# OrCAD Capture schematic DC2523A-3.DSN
size Custom; title: DUAL CHANNEL 8.5A, 18V SYNCHRONOUS STEP-DOWN; rev: 3; note: DC2523A
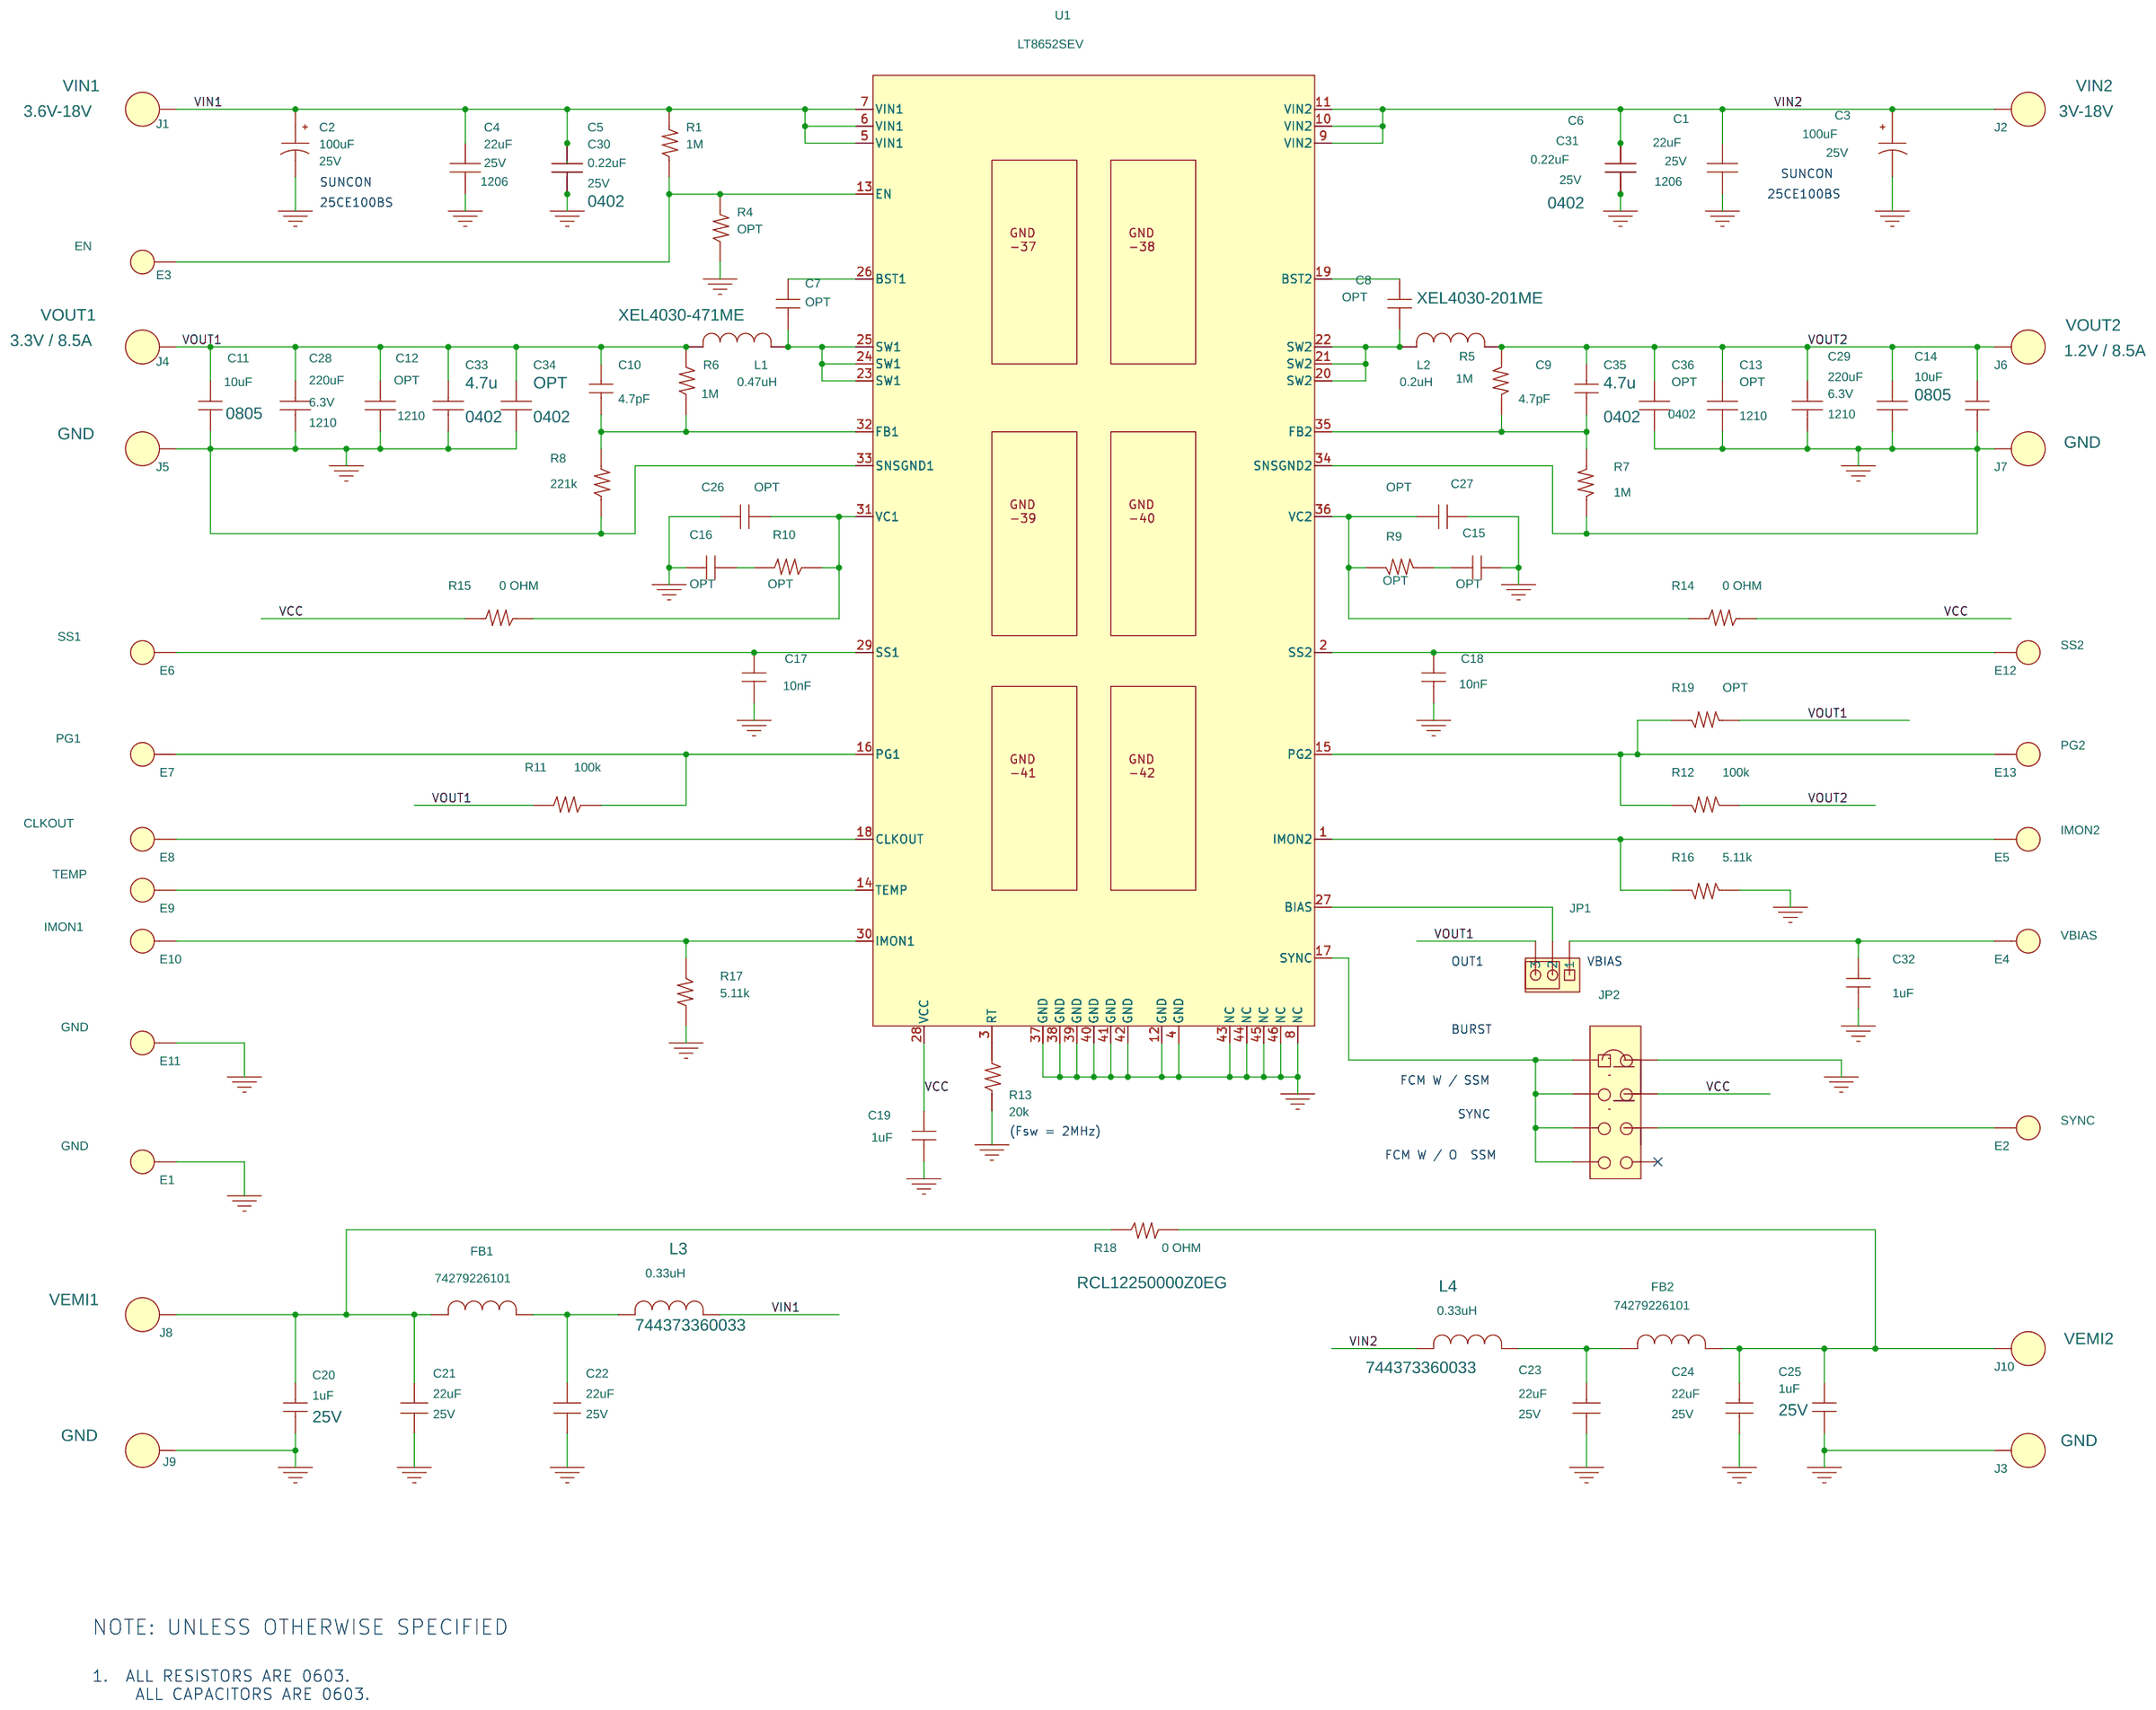
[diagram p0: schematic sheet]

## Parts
C1  22uF  [1206]
C2  100uF  [CAP-CE-BS-6.3X7.7]
C3  100uF  [CAP-CE-BS-6.3X7.7]
C4  22uF  [1206]
C5  0.22uF  [0402]
C6  0.22uF  [0402]
C7  OPT  [0603]
C8  OPT  [0603]
C9  4.7pF  [0603]
C10  4.7pF  [0603]
C11  10uF  [0805]
C12  OPT  [1210]
C13  OPT  [1210]
C14  10uF  [0805]
C15  OPT  [0603]
C16  OPT  [0603]
C17  10nF  [0603]
C18  10nF  [0603]
C19  1uF  [0603]
C20  1uF  [0603]
C21  22uF  [1210]
C22  22uF  [1210]
C23  22uF  [1210]
C24  22uF  [1210]
C25  1uF  [0603]
C26  OPT  [0603]
C27  OPT  [0603]
C28  220uF  [1210]
C29  220uF  [1210]
C30  0.22uF  [0402]
C31  0.22uF  [0402]
C32  1uF  [0603]
C33  4.7u  [0402]
C34  OPT  [0402]
C35  4.7u  [0402]
C36  OPT  [0402]
E1  PAD150-094  [PAD150-094]
E2  PAD150-094  [PAD150-094]
E3  PAD150-094  [PAD150-094]
E4  PAD150-094  [PAD150-094]
E5  PAD150-094  [PAD150-094]
E6  PAD150-094  [PAD150-094]
E7  PAD150-094  [PAD150-094]
E8  PAD150-094  [PAD150-094]
E9  PAD150-094  [PAD150-094]
E10  PAD150-094  [PAD150-094]
E11  PAD150-094  [PAD150-094]
E12  PAD150-094  [PAD150-094]
E13  PAD150-094  [PAD150-094]
FB1  74279226101  [BEAD74279226101]
FB2  74279226101  [BEAD74279226101]
J1  BANANA-JACK  [KEY-575-4]
J2  BANANA-JACK  [KEY-575-4]
J3  BANANA-JACK  [KEY-575-4]
J4  BANANA-JACK  [KEY-575-4]
J5  BANANA-JACK  [KEY-575-4]
J6  BANANA-JACK  [KEY-575-4]
J7  BANANA-JACK  [KEY-575-4]
J8  BANANA-JACK  [KEY-575-4]
J9  BANANA-JACK  [KEY-575-4]
J10  BANANA-JACK  [KEY-575-4]
JP1  JP3X1/079  [JP3X1/079]
JP2  JP2X3/079  [JP2X4/079]
L1  0.47uH  [IND-XEL4030]
L2  0.2uH  [IND-XEL4030]
L3  0.33uH  [IND-744373360033]
L4  0.33uH  [IND-744373360033]
R1  1M  [0603]
R4  OPT  [0603]
R5  1M  [0603]
R6  1M  [0603]
R7  1M  [0603]
R8  221k  [0603]
R9  OPT  [0603]
R10  OPT  [0603]
R11  100k  [0603]
R12  100k  [0603]
R13  20k  [0603]
R14  0 OHM  [0603]
R15  0 OHM  [0603]
R16  5.11k  [0603]
R17  5.11k  [0603]
R18  0 OHM  [RES-RCL1225E3]
R19  OPT  [0603]
U1  LT8652SEV  [LGA-36/46-7X4]

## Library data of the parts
C1 = UMK325BJ105MH: CAP., 22uF, X5R, 25V, ±10%, 1206; 1st Part Field: 25V; 2nd Part Field: ±10%,; 3rd Part Field: X5R,; 4th Part Field: MURATA,; 5th Part Field: GRM31CR61H106KA12L; Part Number: MURATA, GRM31CR61H106KA12L
C2 = 50CE10BSS_1: CAP., 100uF, ALUM, 25V; 1st Part Field: 25V; 2nd Part Field: ±10%,; 3rd Part Field: Alum,; 4th Part Field: SUNCON,; 5th Part Field: 25CE100BS; 6th Part Field: (Opt); Part Number: SUN ELECT., 25CE22BS
C3 = 50CE10BSS: CAP., 100uF, ALUM, 25V; 1st Part Field: 25V; 2nd Part Field: ±10%,; 3rd Part Field: Alum,; 4th Part Field: SUNCON,; 5th Part Field: 25CE100BS; 6th Part Field: (Opt); Part Number: SUN ELECT., 25CE22BS
C4 = UMK325BJ105MH_0: CAP., 22uF, X5R,25V, ±10%, 1206; 1st Part Field: 25V; 2nd Part Field: ±10%,; 3rd Part Field: X5R,; 4th Part Field: MURATA,; 5th Part Field: GRM31CR61H106KA12L; Part Number: MURATA, GRM31CR61H106KA12L
C5 C6 = UMK325BJ105MH: CAP.,  0.22uF,X5R,25V,±10%,0402; 1st Part Field: 25V
C7 C8 = CAP-NP: CAP.,  OPT, 0603; 1st Part Field: 25V; 2nd Part Field: ±10%,; 3rd Part Field: X7R,; 4th Part Field: MURATA,; 5th Part Field: GRM188R71E104KA01D; 7th Part Field: Cap.,; Part Number: MURATA, GRM188R71E104KA01D
C9 C10 = CAP-NP: CAP., 4.7pF, C0G, 50V, ±0.25pF, 0603; 1st Part Field: 50V; 2nd Part Field: ±0.25pF,; 3rd Part Field: C0G; 4th Part Field: MURATA,; 5th Part Field: GRM1885C1H4R7CA01D; 7th Part Field: Cap.,; Part Number: MURATA, GRM1885C1H4R7CA01D
C11 C14 = CAP-NP: CAP., 10uF, X7R, 10V, 10%, 0805; 1st Part Field: 10V; 2nd Part Field: ±10%,; 3rd Part Field: X7R,; 4th Part Field: MURATA,; 5th Part Field: GRM21BR71A106KE51K; 7th Part Field: Cap.,; Part Number: MURATA, GRM21BR71A106KE51K
C12 C13 = UMK325BJ105MH: CAP.,OPT,1210
C15 = CAP-NP: CAP., 1000pF,25V, 0603; 1st Part Field: TBD; 7th Part Field: Cap.,; Discription: CAP., 1000pF, 25V 0603
C16 = CAP-NP: 1st Part Field: TBD; 7th Part Field: Cap.,; Discription: CAP., 1000pF, 25V 0603
C17 = CAP-NP: CAP., 10nF, X7R, 25V, 10%, 0603; 1st Part Field: 25V; 2nd Part Field: ±10%,; 3rd Part Field: X7R,; 4th Part Field: MURATA,; 5th Part Field: GRM188R71E103KA01D; 7th Part Field: Cap.,; Part Number: MURATA, GRM188R71E103KA01D
C18 = CAP-NP: CAP., 10nF, X7R, 25V, 10%, 0603; 1st Part Field: 25V; 2nd Part Field: ±10%,; 3rd Part Field: X7R,; 4th Part Field: MURATA,; 5th Part Field: GRM188R71E103KA01D; 7th Part Field: CAP.,; Part Number: MURATA, GRM188R71E103KA01D
C19 C20 C25 C32 = CAP-NP: CAP., 1uF, X7R, 25V, 10%, 0603; 1ST PART FIELD: 25V; 2nd Part Field: ±10%,; 3rd Part Field: X7R,; 4th Part Field: MURATA,; 5th Part Field: GRM188R71E105KA12D; 7TH PART FIELD: CAP.,; Part Number: MURATA, GRM188R71E105KA12D
C21-C24 = CAP1210: CAP.,  22uF,X7R, 25V, 10% ,1210; 1ST PART FIELD: 25V; 2nd Part Field: ±10%,; 3RD PART FIELD: X7R,; Part Number: MURATA, GRM32ER71E226KE15L
C26 C27 = CAP-NP: CAP., 100pF, X7R, 25V, 10% 0603; 7th Part Field: Cap.,
C28 C29 = UMK325BJ105MH: CAP.,  220uF, X5R, 6.3V, 20%, 1210; 1st Part Field: 6.3V; 2nd Part Field: ±20%; 3rd Part Field: X5R; Part Number: Taiyo Yuden ,JMK325ABJ227MM-T
C30 = UMK325BJ105MH: CAP.,  0.22uF,X5R,25V,±10%,0402; 1st Part Field: 25V; Part Number: MURATA, GRM155R71H104KE14J
C31 = UMK325BJ105MH: CAP.,  0.22uF,X5R,25V,±10%,0402; 1st Part Field: 25V,; 2nd Part Field: ±10%,; 3rd Part Field: X7R,; Part Number: MURATA, GRM155R71H104
C33 C35 C36 = UMK325BJ105MH: CAP.,OPT,0402
C34 = UMK325BJ105MH: CAP., OPT, 0402
E1 = E: TESTPOINT, TURRET, .094"; 9th Part Field: GND; Discription: TESTPOINT, TURRET, .094"; Part Number: MILL-MAX, 2501-2-00-80-00-00-07-0
E2 = E: TESTPOINT, TURRET, .094"; 9th Part Field: SYNC; Part Number: MILL-MAX, 2501-2-00-80-00-00-07-0
E3 = E: TESTPOINT, TURRET, .094"; 9th Part Field: EN; Discription: TESTPOINT, TURRET, .094"; Part Number: MILL-MAX, 2501-2-00-80-00-00-07-0
E4 = E: TESTPOINT, TURRET, .094"; 9th Part Field: VBIAS; Part Number: MILL-MAX, 2501-2-00-80-00-00-07-0
E5 = E: TESTPOINT, TURRET, .094"; 9th Part Field: IMON2; Part Number: MILL-MAX, 2501-2-00-80-00-00-07-0
E6 = E: TESTPOINT, TURRET, .094"; 9th Part Field: SS1; Part Number: MILL-MAX, 2501-2-00-80-00-00-07-0
E7 = E: TESTPOINT, TURRET, .094"; 9th Part Field: PG1; Part Number: MILL-MAX, 2501-2-00-80-00-00-07-0
E8 = E: TESTPOINT, TURRET, .094"; 9th Part Field: CLKOUT; Part Number: MILL-MAX, 2501-2-00-80-00-00-07-0
E9 = E: TESTPOINT, TURRET, .094"; 9th Part Field: TEMP; Part Number: MILL-MAX, 2501-2-00-80-00-00-07-0
E10 = E: TESTPOINT, TURRET, .094"; 9th Part Field: IMON1; Part Number: MILL-MAX, 2501-2-00-80-00-00-07-0
E11 = E: TESTPOINT, TURRET, .094"; 9th Part Field: GND; Part Number: MILL-MAX, 2501-2-00-80-00-00-07-0
E12 = E: TESTPOINT, TURRET, .094"; 9th Part Field: SS2; Part Number: MILL-MAX, 2501-2-00-80-00-00-07-0
E13 = E: TESTPOINT, TURRET, .094"; 9th Part Field: PG2; Part Number: MILL-MAX, 2501-2-00-80-00-00-07-0
FB1 FB2 = IND-TOKO-DB320C: FERRITE BEAD 100OHM 1812 ILN; 4TH PART FIELD: Coilcraft,; 5TH PART FIELD: MPZ2012S300A; Part Number: Wurth Elektronik, 74279226101
J1 = BANANA-JACK: BANANA JACK; 10th Part Field: 3.6V-18V; 9TH Part Field: VIN1; Part Number: KEYSTONE, 575-4
J2 = BANANA-JACK: BANANA JACK; 10th Part Field: 3V-18V; 9TH Part Field: VIN2; Part Number: KEYSTONE, 575-4
J3 J5 J7 J9 = BANANA-JACK: BANANA JACK; 9TH Part Field: GND; Part Number: KEYSTONE, 575-4
J4 = BANANA-JACK: BANANA JACK; 10th Part Field: 3.3V / 8.5A; 9TH Part Field: VOUT1; Part Number: KEYSTONE, 575-4
J6 = BANANA-JACK: BANANA JACK; 10th Part Field: 1.2V / 8.5A; 9TH Part Field: VOUT2; Part Number: KEYSTONE, 575-4
J8 = BANANA-JACK: BANANA JACK; 9TH Part Field: VEMI1; Part Number: KEYSTONE, 575-4
J10 = BANANA-JACK: BANANA JACK; 9TH Part Field: VEMI2; Part Number: KEYSTONE, 575-4
JP1 = JP3X1_0: HEADER 3 PIN  0.079 SINGLE ROW
JP2 = JP2X3_079_7: HEADER, 2X4, 0.079 DOUBLE ROW; Part Number: Wurth Elektronik, 62000821121
L1 = IND: COILCRAFT, INDUCTOR,0.47uH, XEL4030ME; 2nd Part Field: XEL4030-471ME; 7TH PART FIELD: COILCRAFT; Part Number: COILCRAFT, XAL5030-601ME
L2 = IND: COILCRAFT, INDUCTOR,0.2uH, XEL4030-201; 2nd Part Field: XEL4030-201ME; 7TH PART FIELD: COILCRAFT; Part Number: COILCRAFT, XAL5030-331ME
L3 = IND-TOKO-DB320C: FIXED IND., 0.33uH, 16.5A, 5mOHM; 4TH PART FIELD: Coilcraft,; 5TH PART FIELD: 744373360033; Part Number: Wurth Elektronik 744373360033
L4 = IND-TOKO-DB320C: FIXED IND., 330nH, 10.6A, 5 mOHM SMD; 4TH PART FIELD: Coilcraft,; 5TH PART FIELD: 744373360033; Part Number: Wurth Elektronik , 744373360033
R1 R7 = R: RES., 1M, 1/10W, 1%,  0603; 2nd Part Field: ±1%; 3rd Part Field: 1/10W; 7th Part Field: RES.,; Part Number: VISHAY, CRCW06031M00FKEA
R4 = R: RES., OPT, 0603; 7th Part Field: RES.,
R5 = R: RES., 1M, 1/10W, 1%,  0603; 2nd Part Field: ±1%; 3rd Part Field: 1/10W; 7th Part Field: RES.; Part Number: VISHAY, CRCW06031M00FKEA
R6 = R: RES., 1M, 1/10W, 1%,  0603; 2nd Part Field: ±1%; 3rd Part Field: 1/10W; 4th Part Field: VISHAY,; 5th Part Field: CRCW06031M00FKEA; 7th Part Field: RES.,; Part Number: VISHAY, CRCW06031M00FKEA
R8 = R: RES., 221k, 1/10W, 1%,  0603; 2nd Part Field: ±1%; 3rd Part Field: 1/10W; 7th Part Field: RES.,; Part Number: VISHAY, CRCW0603221KFKEA
R9 = R: RES., 3k,1/10W, 1%  0603; 7th Part Field: RES.,
R10 = R: RES.,2k, 0603; 7th Part Field: RES.,
R11 R12 R19 = R: RES., 100k, 1/10W, 1%,  0603; 2nd Part Field: ±1%; 3rd Part Field: 1/10W; 4th Part Field: VISHAY,; 5th Part Field: CRCW0603100KFKEA; 7th Part Field: RES.,; Part Number: VISHAY, CRCW0603100KFKEA
R13 = R: RES., 20k, 1/10W,1%,  0603; 2nd Part Field: ±1%; 3rd Part Field: 1/10W; 4th Part Field: VISHAY,; 5th Part Field: CRCW060318K2FKEA; 7th Part Field: RES.,; Part Number: VISHAY, CRCW060318K2FKEA
R14 = R: RES.,OPT, 0603; 7th Part Field: RES.,
R15 = R: RES., 0 OHM, 1/10W,   0603; 7th Part Field: RES.,
R16 = R: RES.,5.17k, 1/10W, 1%,  0603; 2nd Part Field: ±1%; 3rd Part Field: 50mV/A; 4th Part Field: VISHAY,; 7th Part Field: RES.,; Part Number: VISHAY, CRCW06033K00FKEA
R17 = R: RES., 5.17k, 1/10W, 1%,  0603; 2nd Part Field: ±1%; 3rd Part Field: 50mV/A; 4th Part Field: VISHAY,; 7th Part Field: RES.,; Part Number: VISHAY, CRCW06033K00FKEA
R18 = R: RES., RCL12250000Z0EG ,1225,VISHEY; 1st Part Field: 1225; 7th Part Field: RCL12250000Z0EG
U1 = LT8650_41: I.C. LT8652SEV

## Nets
GND: C1.2 C2.2 C3.2 C4.2 C5.2 C6.2 C11.2 C12.2 C13.2 C14.2 C15.1 C16.1 C17.2 C18.2 C19.2 C20.2 C21.2 C22.2 C23.2 C24.2 C25.2 C26.1 C27.1 C28.2 C29.2 C30.2 C31.2 C32.2 C33.2 C34.2 C35.2 C36.2 E1.1(A) E11.1(A) J3.1 J5.1 J7.1 J9.1 JP2.2 R4.1 R7.1 R8.1 R13.1 R16.1 R17.2 U1.4(GND) U1.8(NC) U1.12(GND) U1.33(SNSGND1) U1.34(SNSGND2) U1.37(GND) U1.38(GND) U1.39(GND) U1.40(GND) U1.41(GND) U1.42(GND) U1.43(NC) U1.44(NC) U1.45(NC) U1.46(NC)
VCC: C19.1 JP2.4 R14.1 R15.2 U1.28(VCC)
VIN1: C2.1 C4.1 C5.1 C30.1 J1.1 L3.2 R1.2 U1.5(VIN1) U1.6(VIN1) U1.7(VIN1)
VIN2: C1.1 C3.1 C6.1 C31.1 J2.1 L4.1 U1.9(VIN2) U1.10(VIN2) U1.11(VIN2)
VOUT1: C10.1 C11.1 C12.1 C28.1 C33.1 C34.1 J4.1 JP1.3 L1.2 R6.2 R11.2 R19.2
VOUT2: C9.1 C13.1 C14.1 C29.1 C35.1 C36.1 J6.1 L2.2 R5.2 R12.2
N16959193: C20.1 C21.1 FB1.1 J8.1 R18.1
N16959197: C22.1 FB1.2 L3.1
N16959806: E3.1(A) R1.1 R4.2 U1.13(EN)
N16960028: C7.2 L1.1 U1.23(SW1) U1.24(SW1) U1.25(SW1)
N16964653: C17.1 E6.1(A) U1.29(SS1)
N16964941: E7.1(A) R11.1 U1.16(PG1)
N16965059: E8.1(A) U1.18(CLKOUT)
N16965347: E9.1(A) U1.14(TEMP)
N16965913: C7.1 U1.26(BST1)
N16967590: C8.2 L2.1 U1.20(SW2) U1.21(SW2) U1.22(SW2)
N16967759: C9.2 R5.1 R7.2 U1.35(FB2)
N16967812: C18.1 E12.1(A) U1.2(SS2)
N16967824: E13.1(A) R12.1 R19.1 U1.15(PG2)
N16967877: C8.1 U1.19(BST2)
N16971448: JP1.2 U1.27(BIAS)
N16972497: C24.1 C25.1 FB2.1 J10.1 R18.2
N16972501: C23.1 FB2.2 L4.2
N16984823: C26.2 R10.1 R15.1 U1.31(VC1)
N16984860: C16.2 R10.2
N16985144: C27.2 R9.1 R14.2 U1.36(VC2)
N16985182: C15.2 R9.2
N16988972: C32.1 E4.1(A) JP1.1
N16992390: E5.1(A) R16.2 U1.1(IMON2)
N16996998: C10.2 R6.1 R8.2 U1.32(FB1)
N16999460: E10.1(A) R17.1 U1.30(IMON1)
N17012644: JP2.1 JP2.3 JP2.5 JP2.7 U1.17(SYNC)
N17069529: E2.1(A) JP2.6
N17225007: R13.2 U1.3(RT)

Not connected (* = marked no-connect by the designer): JP2 8*

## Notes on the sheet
- SUNCON
- SUNCON
- 25CE100BS
- 25CE100BS
- OUT1
- VBIAS
- BURST
- FCM W / SSM
- SYNC
- (Fsw = 2MHz)
- FCM W / O  SSM
- NOTE: UNLESS OTHERWISE SPECIFIED
- 1.  ALL RESISTORS ARE 0603.
       ALL CAPACITORS ARE 0603.
